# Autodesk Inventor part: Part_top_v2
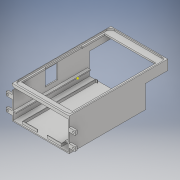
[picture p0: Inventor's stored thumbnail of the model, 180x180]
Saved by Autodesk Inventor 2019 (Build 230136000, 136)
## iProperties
Created: 2019-07
Part Number: Part_top_v2
Material: 常规
Document SubType Name: Modeling
Designer: YOGA3
Density: 1 g/cm^3
Appearance: 默认
Author: YOGA3
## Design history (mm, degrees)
sketch "草图1"
  geometry: L1 (-57.5, 125)-(57.5, 125); L2 (57.5, 125)-(57.5, -125); L3 (57.5, -125)-(-57.5, -125); L4 (-57.5, -125)-(-57.5, 125); L5 (-57.5, 125)-(57.5, -125); L6 (57.5, 125)-(-57.5, -125); 1 further point
  constraints: 12 end point, 2 midpoint, 2 parallel, 1 horizontal, 1 perpendicular
  dimensions: "d0" = 115 distance of L2.end L3.end; "d1" = 250 distance of L1.end L2.end
extrude "拉伸1" new body sketch "草图1" distance "d2" = 6; taper "d3" = 0 deg
sketch "草图2"
  geometry: L1 (55.5, -71)-(-56.5, -71); L2 (-56.5, -71)-(-56.5, 123); L3 (-56.5, 123)-(55.5, 123); L4 (55.5, 123)-(55.5, -71); L5 (55.5, -71)-(-56.5, 123); L6 (-56.5, -71)-(55.5, 123); L7 (57.5, 125)-(-57.5, 125) reference; L8 (57.5, -125)-(57.5, 125) reference; 2 further points
  constraints: 12 end point, 2 midpoint, 2 parallel, 1 horizontal, 1 perpendicular
  dimensions: "d4" = 194 distance of L1.end L2.end; "d5" = 112 distance of L1.start L1.end; "d7" = 2 distance between parallel lines of L8 L4; "d8" = 196 distance between parallel lines of L7 L1
extrude "拉伸2" cut sketch "草图2" distance "d9" = 3; taper "d10" = 0 deg
sketch "草图3"
  geometry: L1 (-72.413, 26)-(-17.038, 26); L2 (-56.5, 123)-(55.5, 123) reference; L3 (-56.5, -71)-(-56.5, 123) reference; L4 (-53.5, -60)-(49.5, -60); L5 (49.5, -60)-(49.5, 109); L6 (49.5, 109)-(-53.5, 109); L7 (-53.5, 109)-(-53.5, 63); L8 (-53.5, 63)-(-54.5, 63); L9 (-53.5, -60)-(-53.5, -11); L10 (-53.5, -11)-(-54.5, -11); L11 (55.5, -71)-(-56.5, -71) reference; L12 (55.5, 123)-(55.5, -71) reference; L13 (-54.5, 63)-(-54.5, -11); 1 further point
  constraints: 18 end point, 6 perpendicular, 2 horizontal, 1 point on line
  dimensions: "d11" = 97 distance between parallel lines of L2 L1; "d13" = 11 distance between parallel lines of L11 L4; "d14" = 14 distance between parallel lines of L2 L6; "d15" = 6 distance between parallel lines of L12 L5; "d16" = 3 distance between parallel lines of L3 L9; "d17" = 60 distance between parallel lines of L11 L10; "d18" = 60 distance between parallel lines of L2 L8; "d40" = 2 distance between parallel lines of L3 L13
fillet "圆角1" dims "d21" = 8
sketch "草图16"
  geometry: L1 (-67.5, -83)-(-57.5, -83); L2 (-57.5, -83)-(-57.5, -75); L3 (-57.5, -75)-(-67.5, -75); L4 (-67.5, -75)-(-67.5, -83); L5 (-57.5, 125)-(-57.5, -125) reference; L6 (57.5, 125)-(-57.5, 125) reference; C1 r 2 at (-64.5, -79); 1 further point
  constraints: 8 end point, 2 parallel, 1 centre point, 1 horizontal, 1 perpendicular
  dimensions: "d86" = 10 distance of L3.end L2.end; "d87" = 8 distance of L1.end L2.end; "d88" = 0 distance between parallel lines of L5 L2; "d89" = 200 distance between parallel lines of L6 L3; "d90" = 4 diameter of C1; "d91" = 4 distance from line of L1 C1.centre; "d92" = 7 distance from line of L2 C1.centre
extrude "拉伸16" join sketch "草图16" distance "d93" = 4; taper "d94" = 0 deg
mirror "镜像3"
extrude "拉伸5" cut sketch "草图3" distance "d41" = 3; taper "d42" = 0 deg
sketch "草图6"
  geometry: L1 (-57.5, -125)-(57.5, -125) reference; C1 r 6 at (0, 100); 3 further points
  constraints: 1 centre point
  dimensions: "d45" = 12 diameter of C1; "d48" = 225 distance from line of L1 C1.centre
extrude "拉伸7" join sketch "草图6" distance "d46" = 25; taper "d47" = 0 deg
node "工作平面1"
sketch "草图7"
  geometry: C1 r 6 at (0, 0) reference; C2 r 3.5 at (0, 0); 1 further point
  constraints: 1 centre point, 1 coincident
  dimensions: "d50" = 7 diameter of C2
extrude "拉伸8" cut sketch "草图7" distance "d51" = 17; taper "d52" = 0 deg
sketch "草图19"
  geometry: L1 (-68.25, -74.506)-(71.663, -74.506); L2 (71.663, -74.506)-(71.663, -128.253); L3 (71.663, -128.253)-(-68.25, -128.253); L4 (-68.25, -128.253)-(-68.25, -74.506); 1 further point
  constraints: 8 end point, 2 parallel, 1 horizontal, 1 perpendicular
extrude "拉伸19" cut sketch "草图19" distance "d105" = 82.75; taper "d106" = 0 deg
sketch "草图20"
  geometry: 1 further point
sketch "草图23"
  geometry: L1 (57.5, -125)-(57.5, 74.506) reference; L2 (57.5, 74.506)-(-57.5, 74.506) reference; L3 (-57.5, 74.506)-(-57.5, -125) reference; L4 (-57.5, -125)-(57.5, -125) reference; 1 further point
extrude "拉伸22" join sketch "草图23" distance "d121" = 60; taper "d122" = 0 deg
sketch "草图24"
  geometry: L1 (55.5, -72.506)-(-55.5, -72.506); L2 (-55.5, -72.506)-(-55.5, 123.494); L3 (-55.5, 123.494)-(55.5, 123.494); L4 (55.5, 123.494)-(55.5, -72.506); L5 (55.5, -72.506)-(-55.5, 123.494); L6 (-55.5, -72.506)-(55.5, 123.494); L7 (-57.5, -74.506)-(57.5, -74.506) reference; L8 (57.5, -74.506)-(57.5, 125) reference; 2 further points
  constraints: 12 end point, 2 midpoint, 2 parallel, 1 horizontal, 1 perpendicular
  dimensions: "d123" = 111 distance of L2.end L3.end; "d124" = 196 distance of L1.end L2.end; "d125" = 2 distance between parallel lines of L7 L1; "d126" = 2 distance between parallel lines of L8 L4
extrude "拉伸23" cut sketch "草图24" distance "d127" = 58; taper "d128" = 0 deg
sketch "草图25"
  geometry: L1 (154.506, -132.229)-(260.651, -132.229); L2 (260.651, -132.229)-(260.651, -20); L3 (260.651, -20)-(154.506, -20); L4 (154.506, -20)-(154.506, -132.229); L5 (154.506, -132.229)-(260.651, -20); L6 (260.651, -132.229)-(154.506, -20); L7 (0, 0)-(199.506, 0) reference; L8 (199.506, 0)-(199.506, -66) reference; 2 further points
  constraints: 12 end point, 2 midpoint, 2 parallel, 1 horizontal, 1 perpendicular
  dimensions: "d129" = 20 distance between parallel lines of L7 L3; "d130" = 45 distance between parallel lines of L8 L4
extrude "拉伸24" cut sketch "草图25" distance "d131" = 200; taper "d132" = 0 deg
sketch "草图26"
  geometry: L1 (2, -6)-(113, -6); L2 (113, -6)-(113, -64); L3 (113, -64)-(2, -64); L4 (2, -64)-(2, -6); L5 (2, -6)-(113, -64); L6 (113, -6)-(2, -64); L7 (0, 0)-(115, 0) reference; L8 (115, 0)-(115, -66) reference; 2 further points
  constraints: 12 end point, 2 midpoint, 2 parallel, 1 horizontal, 1 perpendicular
  dimensions: "d133" = 111 distance of L2.end L3.end; "d134" = 58 distance of L1.end L2.end; "d135" = 6 distance between parallel lines of L7 L1; "d136" = 2 distance between parallel lines of L8 L2
extrude "拉伸25" cut sketch "草图26" distance "d137" = 2; taper "d138" = 0 deg
sketch "草图27"
  geometry: L1 (110, -8)-(135, -8); L2 (135, -8)-(135, -38); L3 (135, -38)-(110, -38); L4 (110, -38)-(110, -8); L5 (110, -8)-(135, -38); L6 (135, -8)-(110, -38); L7 (0, 0)-(0, -20) reference; L8 (0, 0)-(199.506, 0) reference; 2 further points
  constraints: 12 end point, 2 midpoint, 2 parallel, 1 horizontal, 1 perpendicular
  dimensions: "d139" = 25 distance of L2.end L3.end; "d140" = 30 distance of L1.end L2.end; "d141" = 110 distance between parallel lines of L7 L4; "d142" = 8 distance between parallel lines of L8 L1
extrude "拉伸26" cut sketch "草图27" distance "d143" = 2; taper "d144" = 0 deg
sketch "草图28"
  geometry: L1 (39.5, -71.506)-(-39.5, -71.506); L2 (-39.5, -71.506)-(-39.5, 76.494); L3 (-39.5, 76.494)-(39.5, 76.494); L4 (39.5, 76.494)-(39.5, -71.506); L5 (39.5, -71.506)-(-39.5, 76.494); L6 (-39.5, -71.506)-(39.5, 76.494); L7 (55.5, -74.506)-(-55.5, -74.506) reference; L8 (38.5, -70.506)-(-38.5, -70.506); L9 (-38.5, -70.506)-(-38.5, 75.494); L10 (-38.5, 75.494)-(38.5, 75.494); L11 (38.5, 75.494)-(38.5, -70.506); L12 (38.5, -70.506)-(-38.5, 75.494); L13 (-38.5, -70.506)-(38.5, 75.494); L14 (-35.5, 76.494)-(-35.5, 75.494); L15 (35.5, 75.494)-(35.5, 76.494); 3 further points
  constraints: 28 end point, 4 midpoint, 4 parallel, 4 perpendicular, 4 point on line, 2 horizontal
  dimensions: "d145" = 79 distance of L2.end L3.end; "d146" = 148 distance of L1.end L2.end; "d147" = 3 distance between parallel lines of L7 L1; "d148" = 77 distance of L9.end L10.end; "d149" = 146 distance of L8.end L9.end; "d150" = 4 distance between parallel lines of L2 L14; "d151" = 4 distance between parallel lines of L4 L15
extrude "拉伸27" join sketch "草图28" distance "d152" = 5; taper "d153" = 0 deg
sketch "草图29"
  geometry: L1 (-12, -48)-(0, -48); L2 (0, -48)-(0, -56); L3 (0, -56)-(-12, -56); L4 (-12, -56)-(-12, -48); L5 (-12, -48)-(0, -56); L6 (0, -48)-(-12, -56); L7 (0, -66)-(0, 0) reference; L8 (115, -66)-(0, -66) reference; L9 (-12, -20)-(0, -20); L10 (0, -20)-(0, -28); L11 (0, -28)-(-12, -28); L12 (-12, -28)-(-12, -20); L13 (-12, -20)-(0, -28); L14 (0, -20)-(-12, -28); L15 (0, 0)-(115, 0) reference; C1 r 2 at (-9, -24); C2 r 2 at (-9, -52); 3 further points
  constraints: 24 end point, 4 midpoint, 4 parallel, 2 centre point, 2 horizontal, 2 perpendicular
  dimensions: "d154" = 12 distance of L2.end L3.end; "d155" = 8 distance of L1.end L2.end; "d156" = 0 distance between parallel lines of L7 L2; "d157" = 10 distance between parallel lines of L8 L3; "d158" = 12 distance of L10.end L11.end; "d159" = 8 distance of L9.end L10.end; "d160" = 0 distance between parallel lines of L7 L10; "d162" = 4 diameter of C1; "d163" = 4 diameter of C2; "d164" = 3 distance from line of L12 C1.centre; "d165" = 3 distance from line of L4 C2.centre; "d168" = 38 distance between parallel lines of L8 L11; "d169" = 0 vertical distance of point (-6, -24) C1.centre
extrude "拉伸28" join sketch "草图29" distance "d166" = 4; taper "d167" = 0 deg
mirror "镜像5"
sketch "草图30"
  geometry: L1 (-17, 0)-(94, 0) reference; L2 (28.5, 10)-(48.5, 10); L3 (48.5, 10)-(48.5, 0); L4 (48.5, 0)-(28.5, 0); L5 (28.5, 0)-(28.5, 10); L6 (0, 5)-(77, 5) reference; L7 (28.5, 10)-(48.5, 0); L8 (48.5, 10)-(28.5, 0); 2 further points
  constraints: 12 end point, 3 midpoint, 2 parallel, 1 horizontal, 1 perpendicular, 1 point on line
  dimensions: "d170" = 20 distance of L3.end L4.end
extrude "拉伸29" cut sketch "草图30" distance "d171" = 4; taper "d172" = 0 deg
sketch "草图31"
  geometry: L1 (0, 0)-(0, -20) reference; L2 (0, 0)-(115, 0) reference; C1 r 4 at (0, -8); 1 further point
  constraints: 1 centre point, 1 point on line
  dimensions: "d173" = 8 diameter of C1; "d176" = 8 distance from line of L2 C1.centre
extrude "拉伸30" cut sketch "草图31" distance "d174" = 6; taper "d175" = 0 deg
sketch "草图32"
  geometry: L1 (2, -49)-(8, -49); L2 (8, -49)-(8, -47); L3 (8, -47)-(2, -47); L4 (2, -47)-(2, -49); L5 (2, -64)-(2, -11.464) reference; L6 (113, -64)-(2, -64) reference; 1 further point
  constraints: 8 end point, 2 parallel, 1 horizontal, 1 perpendicular
  dimensions: "d177" = 6 distance of L3.end L2.end; "d178" = 2 distance of L1.end L2.end; "d179" = 0 distance between parallel lines of L5 L4; "d180" = 15 distance between parallel lines of L6 L1
extrude "拉伸31" join sketch "草图32" distance "d181" = 150; taper "d182" = 0 deg
mirror "镜像6"
node "实体1"
other parameters: "d49" = -8
